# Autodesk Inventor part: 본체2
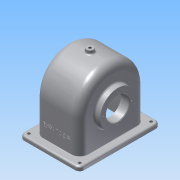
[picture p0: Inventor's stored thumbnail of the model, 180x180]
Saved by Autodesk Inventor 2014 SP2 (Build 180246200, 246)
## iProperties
Created: 2016-01
Part Number: 본체2
Material: 알루미늄 6061
Document SubType Name: Modeling
Designer: User
Mass: 842.835 g
Surface Area: 990.698 cm^2
Volume: 311.009 cm^3
Density: 2.71 g/cm^3
Appearance: 알루미늄 - 평지
Author: User
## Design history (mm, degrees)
sketch "스케치1"
  geometry: L1 (-57, 0)-(57, 0); L2 (57, 0)-(57, -64); L3 (57, -64)-(-57, -64); L4 (-57, -64)-(-57, 0); C1 r 57 at (0, 0); 2 further points
  constraints: 8 end point, 2 coincident, 2 parallel, 1 centre point, 1 horizontal, 1 midpoint, 1 perpendicular
  dimensions: "d0" = 114 diameter of C1; "d1" = 114 distance of L2.end L3.end; "d2" = 64 distance of L1.end L2.end
extrude "돌출1" new body sketch "스케치1" stored distance "d3" = 77; taper "d4" = 0 deg
feature "쉘1" dims "d7" = 6
sketch "스케치3"
  geometry: L1 (114, 0)-(114, -77) reference; L2 (0, 0)-(114, 0) reference; L3 (0, 0)-(0, -77) reference; L4 (114, -77)-(0, -77) reference; L5 (-13, 13.5)-(127, 13.5); L6 (127, 13.5)-(127, -90.5); L7 (127, -90.5)-(-13, -90.5); L8 (-13, -90.5)-(-13, 13.5); 3 further points
  constraints: 8 end point, 2 midpoint, 2 parallel, 1 horizontal, 1 horizontal alignment, 1 perpendicular, 1 vertical alignment
  dimensions: "d8" = 140 distance of L5.start L5.end; "d9" = 104 distance of L5.end L6.end
extrude "돌출2" join sketch "스케치3" distance "d10" = 7; taper "d11" = 0 deg
fillet "모깎기1" dims "d12" = 14
node "작업 평면1"
sketch "스케치6"
  geometry: C1 r 6 at (0, 0); 1 further point
  constraints: 1 centre point, 1 coincident
  dimensions: "d36" = 12 diameter of C1
extrude "돌출4" join sketch "스케치6" stored distance "d37" = 10; taper "d38" = 0 deg
hole "구멍2" diameter "d41" = 4.459; stored, may be unused: countersink angle "d45" = 90 deg, drill point angle "d47" = 118 deg; dims "d39" = 10, "d40" = 10, "d42" = 6, "d43" = 4, "d44" = 2, "d46" = 63
fillet "모깎기4" dims "d77" = 8
sketch "스케치9"
  geometry: A1 r 8 centre (119, 82.5) between (127, 82.5) and (119, 90.5) reference; A2 r 8 centre (-5, 82.5) between (-5, 90.5) and (-13, 82.5) reference; A3 r 8 centre (-5, -5.5) between (-13, -5.5) and (-5, -13.5) reference; A4 r 8 centre (119, -5.5) between (119, -13.5) and (127, -5.5) reference; 1 further point
hole "구멍5" sketch "스케치9" at (119, 82.5), (-5, 82.5), (119, -5.5), (-5, -5.5) diameter "d78" = 5; stored, may be unused: countersink angle "d82" = 90 deg, drill point angle "d84" = 118 deg; dims "d79" = 7, "d80" = 4, "d81" = 2, "d83" = 9
fillet "모깎기5" dims "d85" = 3
sketch "스케치10"
  geometry: L1 (49, 0)-(49, -57) reference; L2 (0, 0)-(49, 0) reference; L3 (0, -57)-(0, 0) reference; L4 (-1.387, -30.398)-(50.387, -30.398); L5 (50.387, -30.398)-(50.387, -37.602); L6 (50.387, -37.602)-(-1.387, -37.602); L7 (-1.387, -37.602)-(-1.387, -30.398); L8 (0, -34)-(49, -34); L9 (-19.5, -64)-(68.5, -64) reference; L10 (24.5, 0)-(24.5, -54); L11 (-14, 0)-(-14, -57) reference; L12 (68.5, -57)-(-19.5, -57) reference; 4 further points
  constraints: 4 end point, 4 midpoint, 2 point on line, 1 horizontal alignment, 1 perpendicular, 1 vertical alignment, 2 other
  dimensions: "d86" = 30 distance between parallel lines of L9 L8; "d87" = 38.5 distance between parallel lines of L11 L10
feature "엠보싱1" sketch "스케치10" dims "d9" = 104, "d88" = 0.5, "d89" = 0
sketch "스케치11"
  geometry: L1 (-51, -64)-(-51, 0) reference; L2 (51, -64)-(-51, -64) reference; L3 (51, 0)-(51, -64) reference; C1 r 20 at (0, -4) reference; A1 r 51 centre (0, 0) between (51, 0) and (-51, 0) reference
extrude "돌출5" cut sketch "스케치11" distance "d90" = 1; taper "d91" = 0 deg
sketch "스케치12"
  geometry: L1 (-51, -64)-(-51, 0) reference; L2 (51, -64)-(-51, -64) reference; L3 (51, 0)-(51, -64) reference; C1 r 38.908 at (0, -4) reference; A1 r 51 centre (0, 0) between (51, 0) and (-51, 0) reference
extrude "돌출6" cut sketch "스케치12" distance "d92" = 1; taper "d93" = 0 deg
sketch "스케치13"
  geometry: L1 (-4, 43.197)-(-4, -48.942); L2 (-64, -33.5)-(-64, 33.5) reference; L3 (16, 35.5)-(30.899, 35.5); L4 (24, 35.5)-(24, 19.5); L5 (24, 19.5)-(16, 19.5); L6 (16, 19.5)-(16, 35.5); L7 (0, 38.5)-(43, 38.5) reference; L8 (24, 19.5)-(39.943, 38.5); L9 (30.899, 35.5)-(33.416, 38.5); L10 (-4, 33.5)-(16, 33.5); L11 (-4, 38.5)-(33.416, 38.5); L12 (-4, 38.5)-(-4, 33.5); 1 further point
  constraints: 20 end point, 6 point on line, 3 parallel, 2 perpendicular, 1 collinear, 1 horizontal, 1 vertical
  dimensions: "d95" = 60 distance between parallel lines of L1 L2; "d96" = 20 distance between parallel lines of L1 L6; "d99" = 50 deg angle of L8 L5; "d100" = 5 distance between parallel lines of L8 L9; "d102" = 5 distance between parallel lines of L10 L11; "d103" = 56 diameter of L4 L1; "d104" = 19 distance between parallel lines of L11 L5; "d105" = 3 distance between parallel lines of L11 L3
revolve "회전3" stored, may be unused: angle "d106" = 90 deg
revolve "회전4" stored, may be unused: angle "d107" = 90 deg
sketch "스케치14"
  geometry: C1 r 20 at (0, -4) reference; C2 r 31 at (0, -4)
  constraints: 1 centre point, 1 coincident
  dimensions: "d108" = 62 diameter of C2
extrude "돌출7" join sketch "스케치14" distance "d109" = 10; taper "d110" = 0 deg
hole "구멍6" diameter "d113" = 40; stored, may be unused: countersink angle "d117" = 90 deg, drill point angle "d119" = 118 deg; dims "d111" = 10, "d112" = 10, "d114" = 6, "d115" = 4, "d116" = 2, "d118" = 8
chamfer "모따기3" distance "d120" = 1; stored, may be unused: second distance "d121" = 2, angle "d122" = 45 deg
fillet "모깎기6" dims "d123" = 3
sketch "스케치15"
  geometry: C1 r 31 at (0, 0) reference; 2 further points
  constraints: 1 vertical alignment
  dimensions: "d124" = 24 distance of C1.centre point (0, 24)
hole "구멍7" sketch "스케치15" at (0, 24) diameter "d125" = 2.459; stored, may be unused: countersink angle "d129" = 90 deg, drill point angle "d131" = 118 deg; dims "d126" = 6, "d127" = 4, "d128" = 2, "d130" = 8
sketch "스케치16"
  geometry: C1 r 21 at (0, 0) reference; 2 further points
  constraints: 1 vertical alignment
  dimensions: "d135" = 28 distance of C1.centre point (0, 28)
hole "구멍8" sketch "스케치16" at (0, 28) diameter "d136" = 2.459; stored, may be unused: countersink angle "d140" = 90 deg, drill point angle "d142" = 118 deg; dims "d137" = 7, "d138" = 4, "d139" = 2, "d141" = 9
fillet "모깎기7" dims "d146" = 9
fillet "모깎기8" dims "d147" = 3
fillet "모깎기9" dims "d148" = 1
sketch "스케치17"
  geometry: L1 (0, -4)-(-70.761, -4); L2 (-70.761, -4)-(-70.761, 71.746); L3 (-70.761, 71.746)-(0, 71.746); L4 (0, 71.746)-(0, -4); C1 r 34 at (0, -4) reference
  constraints: 8 end point, 2 parallel, 1 horizontal, 1 perpendicular
extrude "돌출8" cut sketch "스케치17" stored distance "d149" = 10; taper "d150" = 0 deg
node "솔리드1"
pattern_circular "원형 패턴3" dims angle "d133" = 360 deg
pattern_circular "원형 패턴4" dims angle "d144" = 360 deg
other parameters: "d35" = 63
